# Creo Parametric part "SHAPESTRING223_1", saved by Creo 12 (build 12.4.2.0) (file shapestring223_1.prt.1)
Units: Custom; MM, KILOGRAM, SECS

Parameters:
  PTC_WM_ITERATION = "0"
  PTC_WM_VERSION = "-.0"
  PTC_WM_LIFECYCLE_STATE = "In Work"
  PTC_WM_LIFECYCLE = "MO_CADDocument"
  PTC_WM_CREATED_BY = "Maximilian Roepper (Z0017RMS: MO)"
  PTC_WM_CREATED_ON = "18-Sep-26 11:36:42 AM"
  PTC_WM_MODIFIED_BY = "Maximilian Roepper (Z0017RMS: MO)"
  PTC_WM_MODIFIED_ON = "18-Sep-26 11:36:46 AM"
  PDMLINKNUMBER = "PDM000071455224"
  PTC_WM_NAME = "shapestring223_1.prt"
  PTC_WM_NUMBER = "PDM000071455224"

Other parameters: WEIGHT, WEIGHT_FACTOR, WEIGHT_ADD, _MASS_TEMP, _DIFF_TEMP, MC_ERRORS, SUPPLIER

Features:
  1. coordinate system
  2. datum plane "PRT_YZ"
  3. datum plane "PRT_XY"
  4. datum plane "PRT_XZ"
  5. coordinate system
  6. datum axis
  7. datum axis
  8. datum axis
  9. coordinate system
  10. imported feature
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
Other named items: PRT, SIEMENS_MO, DRW_VIEW_ORG, PRT_X, PRT_Y, PRT_Z, CS0, ROUGH_GROB

Layers: 00_STD_CSYS-KSYS, 01_STD_PLANES-EBENEN, 02_STD_AXES-ACHSEN, 03_STD_CSYS-KSYS, 24_IMPORT_FEAT-IMPORT_KE, INTFCLR

Surfaces: 1 plane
